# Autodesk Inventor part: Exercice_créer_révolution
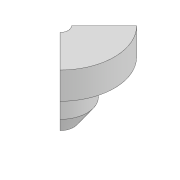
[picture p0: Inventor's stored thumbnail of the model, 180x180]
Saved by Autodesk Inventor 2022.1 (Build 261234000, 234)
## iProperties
Created: 2021-06
Part Number: Exercice_créer_révolution
Material: Générique
Document SubType Name: Modeling
Designer: Fabian
Density: 1 g/cm^3
Appearance: Par défaut
Mass: 0.533331 g
Surface Area: 4.74949 cm^2
Volume: 0.533331 cm^3
Author: Fabian
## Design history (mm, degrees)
sketch "Esquisse1"
  geometry: L1 (0, 0)-(0, 15); L2 (1.5, 15)-(10, 15); L3 (10, 15)-(10, 10); L4 (10, 10)-(5, 10); L5 (5, 10)-(5, 3.57); L6 (5, 3.57)-(2.5, 0); L7 (2.5, 0)-(1.5, 0); L8 (1.5, 15)-(1.5, 0)
  constraints: 16 end point, 4 perpendicular, 2 point on line, 1 horizontal, 1 parallel, 1 vertical
  dimensions: "d0" = 15 distance of L1.start L1.end; "d1" = 20 diameter of L3 L1; "d2" = 35 deg angle of L1 L6; "d3" = 5 distance of L2.end L3.end; "d4" = 10 diameter of L5 L1; "d5" = 5 diameter of L6.end L1; "d6" = 3 diameter of L8 L1
revolve "Révolution1" sketch "Esquisse1" stored, may be unused: angle "d7" = 90 deg
node "Solide1"
